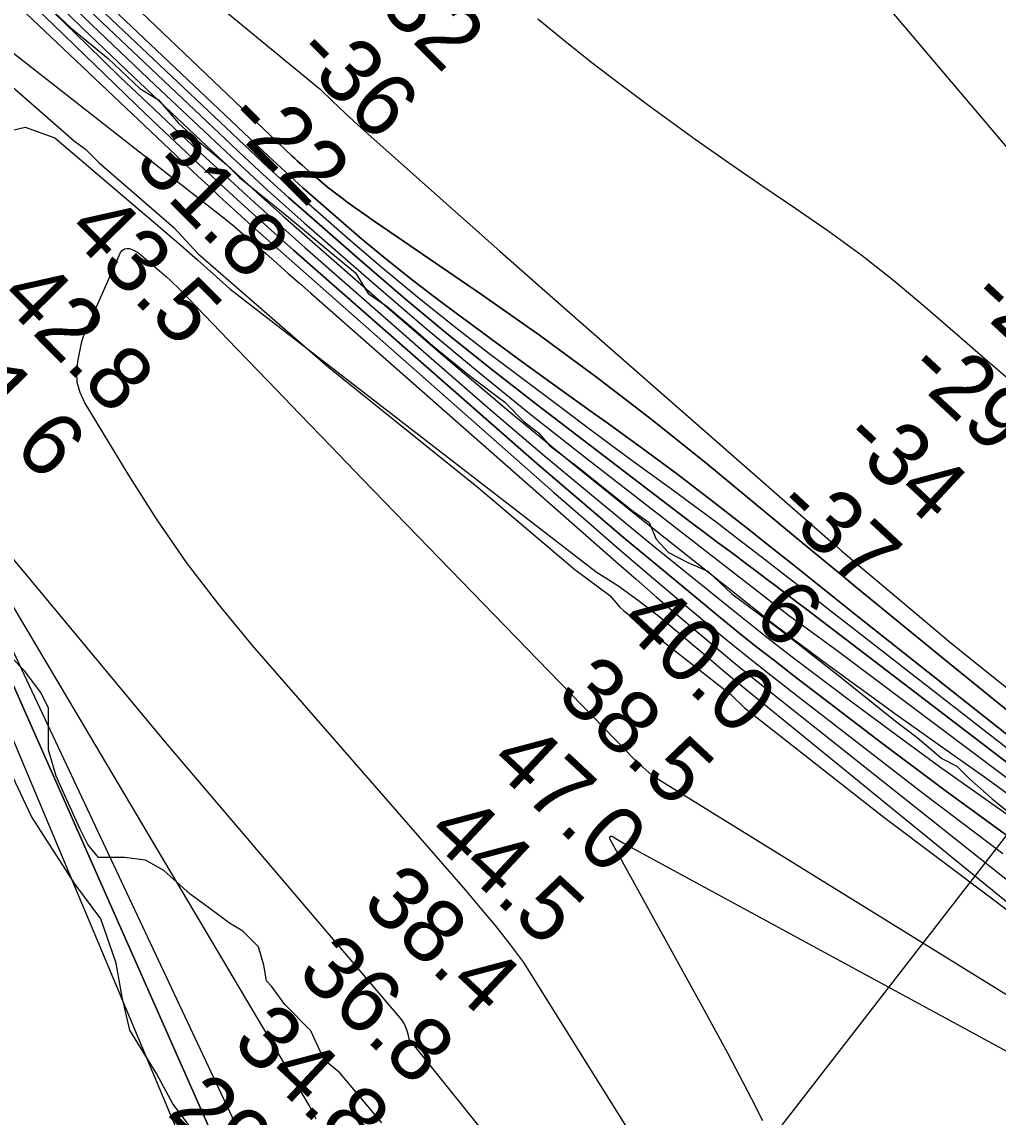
# Model space of a CAD drawing. Extents: x 3161615 to 3199515, y 867541 to 892976.
# Drawn here: x 3182704 to 3183730, y 881302 to 882454 of the extents above; entities that cross this region are included whole.
import ezdxf

# ---------------------------------------------------------------- set-up
doc = ezdxf.new("R2010")
doc.units = 0
for name, color, linetype in [('V-RIVR-EDGE', 7, 'Continuous'), ('V-RIVR-RANG', 7, 'Continuous'), ('V-SITE-VEGE', 7, 'Continuous'), ('V-TOPO-DPTH', 7, 'Continuous'), ('V-TOPO-MAJR', 7, 'Continuous'), ('V-TOPO-MINR', 7, 'Continuous'), ('V-TOPO-WATR', 7, 'Continuous')]:
    doc.layers.add(name, color=color, linetype=linetype)

msp = doc.modelspace()

# ---------------------------------------------------------------- linework, layer by layer
at = {"layer": 'V-RIVR-EDGE'}
for points in [[(3182726.1, 882475.2), (3182755.5, 882447.5), (3182794.6, 882415.5), (3182827.9, 882383.9), (3182847.4, 882371.9), (3182868.3, 882347.6), (3182888.8, 882328.9), (3182918.8, 882304), (3182932.6, 882290.2), (3182984, 882248.6), (3183026.3, 882213.2), (3183054.4, 882190.2), (3183067.7, 882168.2), (3183087.7, 882154.8), (3183120.5, 882127.1), (3183135.7, 882113.2), (3183174.8, 882081.7), (3183211.4, 882053.9), (3183231.9, 882033.4), (3183247.1, 882021.9), (3183258.5, 882008.5), (3183291.8, 881983.1), (3183298, 881977.9), (3183347, 881939.1), (3183363.2, 881927.6), (3183370.8, 881910), (3183383.7, 881896.1), (3183404.1, 881885.6), (3183425.1, 881876.5), (3183450.3, 881852.6), (3183500.3, 881815.2), (3183565.5, 881764), (3183622.1, 881719.1), (3183645, 881701.4), (3183671.2, 881679.4), (3183686.9, 881671.2), (3183700.2, 881657.8), (3183724, 881636.8), (3183748.3, 881617.2)], [(3182845.3, 881348.1), (3182817.3, 881393.5), (3182809.3, 881428.3), (3182802.7, 881464.1), (3182786.6, 881510.8), (3182759.5, 881547.6), (3182713.9, 881618.3), (3182677.4, 881695.2)], [(3182880, 881293.2), (3182862.4, 881316.1), (3182845.3, 881348.1)]]:
    msp.add_lwpolyline(points, dxfattribs=at)
at = {"layer": 'V-RIVR-RANG'}
msp.add_line((3181801.2, 879095.8), (3184051.7, 882002.4), dxfattribs=at)
at = {"layer": 'V-SITE-VEGE'}
for points in [[(3182582.5, 882483.1), (3182759, 882328.7), (3182770.5, 882320), (3182784.9, 882305.8), (3182863.6, 882237.7), (3182888.8, 882210.5), (3183025.9, 882091.1), (3183183.9, 881963.9), (3183285.3, 881878), (3183322.1, 881850.8), (3183332.3, 881838.5), (3183336.3, 881835), (3183449.1, 881746.6), (3183463.7, 881732.6), (3183610.1, 881617.8), (3183727.1, 881529.7), (3183827.7, 881452.8)], [(3183082.3, 881296.3), (3183038.1, 881348.8), (3183021.5, 881362.6), (3183007.7, 881393), (3182980.1, 881420.6), (3182966.3, 881439.9), (3182960.8, 881445.4), (3182958, 881462), (3182952.5, 881481.3), (3182935.9, 881497.9), (3182922.1, 881506.2), (3182900.1, 881522.8), (3182880.7, 881536.6), (3182853.1, 881561.4), (3182833.8, 881572.5), (3182811.7, 881575.2), (3182784.1, 881575.2), (3182773.1, 881589), (3182764.8, 881605.6), (3182751, 881636), (3182739.9, 881660.8), (3182731.7, 881688.5), (3182731.7, 881732.6), (3182723.4, 881749.2), (3182706.8, 881771.3), (3182693, 881785.1)]]:
    msp.add_lwpolyline(points, dxfattribs=at)
at = {"layer": 'V-TOPO-DPTH'}
for points in [[(3183742, 881596.5), (3183674.6, 881645.7), (3183607.8, 881695.8), (3183515.3, 881766.4), (3183495.3, 881781.9), (3183475.3, 881797.6), (3183455.5, 881813.4), (3183435.8, 881829.5), (3183382.5, 881873.5), (3183336.4, 881911.8), (3183290.6, 881950.5), (3183245.1, 881989.6), (3183199.9, 882029), (3182989.4, 882214), (3182965.5, 882235.3), (3182941.6, 882256.7), (3182917.9, 882278.4), (3182894.4, 882300.1), (3182871, 882322.1), (3182847.7, 882344.1), (3182824.5, 882366.2), (3182801.4, 882388.5), (3182368.3, 882807.3)], [(3182509.3, 882800.7), (3183017.5, 882383.2), (3183030.5, 882370.6), (3183043.7, 882358.1), (3183057.1, 882345.8), (3183070.5, 882333.6), (3183124.8, 882285.2), (3183165.5, 882249), (3183206.3, 882212.8), (3183247.2, 882176.7), (3183288.2, 882140.8), (3183553.9, 881907.9), (3183559.8, 881902.9), (3183565.6, 881897.8), (3183571.5, 881892.8), (3183577.3, 881887.8), (3183622.9, 881849.2), (3183651.7, 881825.1), (3183680.6, 881801.1), (3183709.7, 881777.4), (3183739, 881753.9), (3183778.6, 881722.3)], [(3182509.3, 882800.7), (3183017.5, 882383.2), (3183030.5, 882370.6), (3183043.7, 882358.1), (3183057.1, 882345.8), (3183070.5, 882333.6), (3183124.8, 882285.2), (3183165.5, 882249), (3183206.3, 882212.8), (3183247.2, 882176.7), (3183288.2, 882140.8), (3183553.9, 881907.9), (3183559.8, 881902.9), (3183565.6, 881897.8), (3183571.5, 881892.8), (3183577.3, 881887.8), (3183622.9, 881849.2), (3183651.7, 881825.1), (3183680.6, 881801.1), (3183709.7, 881777.4), (3183739, 881753.9)], [(3182579.5, 882702.2), (3182988, 882312.9), (3182990.6, 882310.4), (3182993.2, 882308), (3182995.9, 882305.5), (3182998.5, 882303.2), (3183009, 882293.9), (3183017, 882287), (3183025.1, 882280.3), (3183033.5, 882273.8), (3183041.9, 882267.4), (3183044.5, 882265.6), (3183054.3, 882258.5), (3183064.2, 882251.5), (3183074.1, 882244.5), (3183084.1, 882237.6), (3183187, 882167.3), (3183247.9, 882124.4), (3183308, 882080.5), (3183366.8, 882035), (3183424.9, 881988.4), (3183525.4, 881905.4), (3183539, 881894.2), (3183552.5, 881883), (3183566.1, 881871.9), (3183579.7, 881860.7), (3183667.8, 881788.4), (3183725.6, 881741.3), (3183783.7, 881694.6)], [(3183768.4, 881706.9), (3183725.6, 881741.3), (3183667.8, 881788.4), (3183579.7, 881860.7), (3183566.1, 881871.9), (3183552.5, 881883), (3183539, 881894.2), (3183525.4, 881905.4), (3183424.9, 881988.4), (3183366.8, 882035), (3183308, 882080.5), (3183247.9, 882124.4), (3183187, 882167.3), (3183084.1, 882237.6), (3183074.1, 882244.5), (3183064.2, 882251.5), (3183054.3, 882258.5), (3183044.5, 882265.6), (3183041.9, 882267.4), (3183033.5, 882273.8), (3183025.1, 882280.3), (3183017, 882287), (3183009, 882293.9), (3182998.5, 882303.2), (3182995.9, 882305.5), (3182993.2, 882308), (3182990.6, 882310.4), (3182988, 882312.9), (3182579.5, 882702.2)], [(3182293.8, 882669.9), (3182441, 882190.9), (3182448.4, 882170.4), (3182457, 882150.5), (3182467.3, 882131.5), (3182478.8, 882113), (3182579.7, 881966.6), (3182593.9, 881946.1), (3182608.2, 881925.6), (3182622.7, 881905.3), (3182637.3, 881885), (3182925.1, 881235.7)], [(3183452.3, 882661), (3183796.2, 882255)], [(3183452.3, 882661), (3183796.2, 882255)], [(3183797.7, 881658.7), (3183715.6, 881723.5), (3183582.9, 881828.8), (3183559.9, 881847), (3183536.9, 881865.3), (3183513.9, 881883.6), (3183490.9, 881901.9), (3183464.8, 881922.7), (3183428.5, 881951.1), (3183392, 881979.1), (3183354.9, 882006.5), (3183317.6, 882033.5), (3183303.9, 882043.2), (3183267.5, 882069.3), (3183231.2, 882095.6), (3183195.1, 882122), (3183159.1, 882148.7), (3183144, 882159.9), (3183115.9, 882181.4), (3183088.1, 882203.3), (3183060.9, 882225.9), (3183034.1, 882249), (3182999.3, 882279.6), (3182990.1, 882287.7), (3182981.1, 882295.9), (3182972.1, 882304.2), (3182963.2, 882312.6), (3182707.9, 882554.7)], [(3183797.7, 881658.7), (3183715.6, 881723.5), (3183582.9, 881828.8), (3183559.9, 881847), (3183536.9, 881865.3), (3183513.9, 881883.6), (3183490.9, 881901.9), (3183464.8, 881922.7), (3183428.5, 881951.1), (3183392, 881979.1), (3183354.9, 882006.5), (3183317.6, 882033.5), (3183303.9, 882043.2), (3183267.5, 882069.3), (3183231.2, 882095.6), (3183195.1, 882122), (3183159.1, 882148.7), (3183144, 882159.9), (3183115.9, 882181.4), (3183088.1, 882203.3), (3183060.9, 882225.9), (3183034.1, 882249), (3182999.3, 882279.6), (3182990.1, 882287.7), (3182981.1, 882295.9), (3182972.1, 882304.2), (3182963.2, 882312.6), (3182707.9, 882554.7)], [(3182720.6, 882493.2), (3182766.9, 882447.9), (3182813.6, 882403.1), (3182860.6, 882358.6), (3182910.6, 882311.7), (3182932.9, 882291), (3182955.4, 882270.4), (3182978.1, 882250.1), (3183000.9, 882229.9), (3183085.6, 882155.8), (3183151.2, 882099.2), (3183217.4, 882043.2), (3183284.4, 881988.2), (3183351.9, 881933.8), (3183479.9, 881832.1), (3183487.8, 881825.8), (3183495.9, 881819.6), (3183503.9, 881813.5), (3183512, 881807.4), (3183545.4, 881782.5), (3183570.3, 881764.2), (3183595.2, 881745.9), (3183620.3, 881727.8), (3183645.5, 881709.8), (3183675.6, 881688.6), (3183715.8, 881659.9), (3183755.8, 881631.1)], [(3182720.6, 882493.2), (3182766.9, 882447.9), (3182813.6, 882403.1), (3182860.6, 882358.6), (3182910.6, 882311.7), (3182932.9, 882291), (3182955.4, 882270.4), (3182978.1, 882250.1), (3183000.9, 882229.9), (3183085.6, 882155.8), (3183151.2, 882099.2), (3183217.4, 882043.2), (3183284.4, 881988.2), (3183351.9, 881933.8), (3183479.9, 881832.1), (3183487.8, 881825.8), (3183495.9, 881819.6), (3183503.9, 881813.5), (3183512, 881807.4), (3183545.4, 881782.5), (3183570.3, 881764.2), (3183595.2, 881745.9), (3183620.3, 881727.8), (3183645.5, 881709.8), (3183675.6, 881688.6), (3183715.8, 881659.9), (3183755.8, 881631.1)], [(3182756.3, 882483.9), (3182826.6, 882416.7), (3182937.4, 882312.2), (3182952.9, 882297.7), (3182968.5, 882283.4), (3182984.2, 882269.3), (3183000.1, 882255.2), (3183058.9, 882203.8), (3183104.7, 882164.6), (3183150.9, 882126), (3183197.9, 882088.4), (3183245.4, 882051.3), (3183394.6, 881937.4), (3183408, 881927.2), (3183421.4, 881917.1), (3183434.9, 881907), (3183448.4, 881896.9), (3183453.7, 881893), (3183464.6, 881884.9), (3183475.4, 881876.8), (3183486.1, 881868.7), (3183496.8, 881860.5), (3183507.5, 881852.4), (3183518.3, 881844.2), (3183529, 881836), (3183539.7, 881827.8), (3183856.4, 881585.9)], [(3183856.4, 881585.9), (3183539.7, 881827.8), (3183529, 881836), (3183518.3, 881844.2), (3183507.5, 881852.4), (3183496.8, 881860.5), (3183486.1, 881868.7), (3183475.4, 881876.8), (3183464.6, 881884.9), (3183453.7, 881893), (3183448.4, 881896.9), (3183434.9, 881907), (3183421.4, 881917.1), (3183408, 881927.2), (3183394.6, 881937.4), (3183245.4, 882051.3), (3183197.9, 882088.4), (3183150.9, 882126), (3183104.7, 882164.6), (3183058.9, 882203.8), (3183000.1, 882255.2), (3182984.2, 882269.3), (3182968.5, 882283.4), (3182952.9, 882297.7), (3182937.4, 882312.2), (3182826.6, 882416.7), (3182756.3, 882483.9)], [(3183738.6, 882080.5), (3183714.2, 882101.4), (3183689.9, 882122.4), (3183653.5, 882154), (3183620.7, 882181.5), (3183587.2, 882208.1), (3183552.7, 882233.2), (3183517.5, 882257.5), (3183481.9, 882281.4), (3183446.6, 882305.6), (3183411.6, 882330.3), (3183376.9, 882355.4), (3183361.4, 882366.8), (3183332.2, 882388.7), (3183303.2, 882410.9), (3183274.6, 882433.6), (3183246.3, 882456.7)], [(3183738.6, 882080.5), (3183714.2, 882101.4), (3183689.9, 882122.4), (3183653.5, 882154), (3183620.7, 882181.5), (3183587.2, 882208.1), (3183552.7, 882233.2), (3183517.5, 882257.5), (3183481.9, 882281.4), (3183446.6, 882305.6), (3183411.6, 882330.3), (3183376.9, 882355.4), (3183361.4, 882366.8), (3183332.2, 882388.7), (3183303.2, 882410.9), (3183274.6, 882433.6), (3183246.3, 882456.7)]]:
    msp.add_lwpolyline(points, dxfattribs=at)
at = {"layer": 'V-TOPO-MAJR'}
for points in [[(3182664.5, 882333.1), (3182707.1, 882343.1), (3182738.2, 882332.1), (3182853.9, 882233.7), (3182871.2, 882218.8), (3182888.4, 882203.8), (3182905.3, 882188.6), (3182922.2, 882173.3), (3183307.6, 881875.6), (3183330.4, 881861.3), (3183352.2, 881845.6), (3183373.4, 881829), (3183398.6, 881807.9), (3183406.7, 881801.1), (3183414.8, 881794.3), (3183422.8, 881787.5), (3183430.8, 881780.7), (3183438.9, 881773.8), (3183447, 881767.1), (3183455.1, 881760.3), (3183463.2, 881753.7), (3183998.2, 881317.8)], [(3183646.8, 880717.5), (3183111.1, 881384.2), (3183110.9, 881384.6), (3183110.3, 881387.7), (3183110.1, 881388.2), (3183108.4, 881394.1), (3183107.2, 881397.4), (3183105.7, 881400.6), (3183103.8, 881403.6), (3183101.6, 881406.5), (3182856.5, 881694.4), (3182643, 881951)]]:
    msp.add_lwpolyline(points, dxfattribs=at)
at = {"layer": 'V-TOPO-MINR'}
for points in [[(3182368.3, 882807.3), (3182801.4, 882388.5), (3182824.5, 882366.2), (3182847.7, 882344.1), (3182871, 882322.1), (3182894.4, 882300.1), (3182917.9, 882278.4), (3182941.6, 882256.7), (3182965.5, 882235.3), (3182989.4, 882214), (3183199.9, 882029), (3183245.1, 881989.6), (3183290.6, 881950.5), (3183336.4, 881911.8), (3183382.5, 881873.5), (3183435.8, 881829.5), (3183455.5, 881813.4), (3183475.3, 881797.6), (3183495.3, 881781.9), (3183515.3, 881766.4), (3183607.8, 881695.8), (3183674.6, 881645.7), (3183742, 881596.5)], [(3182509.3, 882800.7), (3183017.5, 882383.2), (3183030.5, 882370.6), (3183043.7, 882358.1), (3183057.1, 882345.8), (3183070.5, 882333.6), (3183124.8, 882285.2), (3183165.5, 882249), (3183206.3, 882212.8), (3183247.2, 882176.7), (3183288.2, 882140.8), (3183553.9, 881907.9), (3183559.8, 881902.9), (3183565.6, 881897.8), (3183571.5, 881892.8), (3183577.3, 881887.8), (3183622.9, 881849.2), (3183651.7, 881825.1), (3183680.6, 881801.1), (3183709.7, 881777.4), (3183739, 881753.9)], [(3183783.7, 881694.6), (3183725.6, 881741.3), (3183667.8, 881788.4), (3183579.7, 881860.7), (3183566.1, 881871.9), (3183552.5, 881883), (3183539, 881894.2), (3183525.4, 881905.4), (3183424.9, 881988.4), (3183366.8, 882035), (3183308, 882080.5), (3183247.9, 882124.4), (3183187, 882167.3), (3183084.1, 882237.6), (3183074.1, 882244.5), (3183064.2, 882251.5), (3183054.3, 882258.5), (3183044.5, 882265.6), (3183041.9, 882267.4), (3183033.5, 882273.8), (3183025.1, 882280.3), (3183017, 882287), (3183009, 882293.9), (3182998.5, 882303.2), (3182995.9, 882305.5), (3182993.2, 882308), (3182990.6, 882310.4), (3182988, 882312.9), (3182579.5, 882702.2)], [(3183469, 879013.6), (3183197.7, 880018.7), (3183198.1, 880021.4), (3183197.8, 880022.8), (3183196, 880027.2), (3183194.9, 880029.5), (3183193.6, 880031.8), (3183192.2, 880034.1), (3183181.6, 880049.9), (3183030.2, 880674), (3182912.2, 881192.2), (3182899.3, 881211.2), (3182615.6, 881886.6), (3182596.4, 881913.9), (3182577.5, 881941.3), (3182558.6, 881968.9), (3182431.4, 882156.4), (3182416.9, 882180.1), (3182403.8, 882204.5), (3182393, 882229.9), (3182383.6, 882256.1), (3182375, 882284.4), (3182269.1, 882673.7)], [(3182925.1, 881235.7), (3182637.3, 881885), (3182622.7, 881905.3), (3182608.2, 881925.6), (3182593.9, 881946.1), (3182579.7, 881966.6), (3182478.8, 882113), (3182467.3, 882131.5), (3182457, 882150.5), (3182448.4, 882170.4), (3182441, 882190.9), (3182293.8, 882669.9)], [(3183452.3, 882661), (3183796.2, 882255)], [(3182707.9, 882554.7), (3182963.2, 882312.6), (3182972.1, 882304.2), (3182981.1, 882295.9), (3182990.1, 882287.7), (3182999.3, 882279.6), (3183034.1, 882249), (3183060.9, 882225.9), (3183088.1, 882203.3), (3183115.9, 882181.4), (3183144, 882159.9), (3183159.1, 882148.7), (3183195.1, 882122), (3183231.2, 882095.6), (3183267.5, 882069.3), (3183303.9, 882043.2), (3183317.6, 882033.5), (3183354.9, 882006.5), (3183392, 881979.1), (3183428.5, 881951.1), (3183464.8, 881922.7), (3183490.9, 881901.9), (3183513.9, 881883.6), (3183536.9, 881865.3), (3183559.9, 881847), (3183582.9, 881828.8), (3183715.6, 881723.5), (3183797.7, 881658.7)], [(3182726.6, 882499.9), (3182784.9, 882443.6), (3182843.6, 882387.7), (3182924.1, 882312), (3182943, 882294.4), (3182962, 882277), (3182981.2, 882259.8), (3183000.5, 882242.7), (3183071.5, 882180.8), (3183126.8, 882133.4), (3183182.7, 882086.6), (3183239.3, 882040.8), (3183296.5, 881995.7), (3183504.9, 881834), (3183506.2, 881833), (3183510, 881830.1), (3183514.8, 881826.6), (3183518.5, 881823.9), (3183522.2, 881821.2), (3183526, 881818.5), (3183529.7, 881815.8), (3183536.6, 881810.7), (3183543.8, 881805.5), (3183550.9, 881800.3), (3183558.1, 881795), (3183565.2, 881789.7), (3183924.2, 881520.7)], [(3182949.6, 881249.7), (3182639.4, 881908.7), (3182629.3, 881922.6), (3182619.2, 881936.5), (3182609.2, 881950.6), (3182599.3, 881964.6), (3182525.9, 882069.6), (3182517.6, 882082.8), (3182510.1, 882096.5), (3182503.8, 882110.8), (3182456.4, 882208.2), (3182369.2, 882483.9)], [(3182756.3, 882483.9), (3182826.6, 882416.7), (3182937.4, 882312.2), (3182952.9, 882297.7), (3182968.5, 882283.4), (3182984.2, 882269.3), (3183000.1, 882255.2), (3183058.9, 882203.8), (3183104.7, 882164.6), (3183150.9, 882126), (3183197.9, 882088.4), (3183245.4, 882051.3), (3183394.6, 881937.4), (3183408, 881927.2), (3183421.4, 881917.1), (3183434.9, 881907), (3183448.4, 881896.9), (3183453.7, 881893), (3183464.6, 881884.9), (3183475.4, 881876.8), (3183486.1, 881868.7), (3183496.8, 881860.5), (3183507.5, 881852.4), (3183518.3, 881844.2), (3183529, 881836), (3183539.7, 881827.8), (3183856.4, 881585.9)], [(3182772.3, 882480.9), (3182950.4, 882312.4), (3182962.6, 882301), (3182974.8, 882289.7), (3182987.2, 882278.6), (3182999.7, 882267.5), (3183046.5, 882226.4), (3183082.8, 882195.3), (3183119.6, 882164.7), (3183157, 882134.9), (3183194.8, 882105.7), (3183267.5, 882050.9), (3183295.1, 882030.2), (3183322.7, 882009.7), (3183350.5, 881989.3), (3183378.3, 881969), (3183385.9, 881963.5), (3183409.9, 881945.9), (3183433.7, 881928.1), (3183457.4, 881910), (3183481, 881891.8), (3183504.5, 881873.5), (3183528, 881855.2), (3183551.5, 881836.9), (3183575, 881818.6), (3183786.8, 881653.6)], [(3183013.3, 881300.1), (3183006.2, 881313.9), (3182635.3, 881938.6), (3182629.3, 881946.6), (3182623.5, 881954.7), (3182617.7, 881962.9), (3182572.8, 882026.2), (3182567.7, 882034.2), (3182563.1, 882042.5), (3182559.3, 882051.1), (3182556.1, 882060.1), (3182523.9, 882140.4), (3182476.6, 882285.8), (3182461.7, 882361), (3182461.8, 882408.6), (3182474.4, 882468.7)], [(3182708.2, 882462.9), (3182865.5, 882313.7), (3182876.9, 882302.9), (3182888.3, 882292.2), (3182899.8, 882281.4), (3182911.2, 882270.7), (3182922.8, 882260.1), (3182934.3, 882249.5), (3182946, 882239), (3182957.7, 882228.6), (3183262.8, 881959.5), (3183296.2, 881930.2), (3183329.7, 881901.2), (3183363.4, 881872.4), (3183397.3, 881843.8), (3183415.6, 881828.5), (3183440.6, 881807.8), (3183465.8, 881787.3), (3183491.1, 881767.1), (3183516.7, 881747.1), (3183651.7, 881642.7), (3183735.1, 881579.5)], [(3182737.8, 882463.5), (3182772.4, 882429.7), (3182807.2, 882396), (3182842.3, 882362.6), (3182877.5, 882329.4), (3182896.7, 882311.5), (3182922.6, 882287.5), (3182948.6, 882263.7), (3182974.8, 882240.2), (3183001.2, 882216.8), (3183139.6, 882095.4), (3183196.2, 882046.4), (3183253.2, 881997.8), (3183310.8, 881949.8), (3183368.7, 881902.3), (3183457.1, 881830.7), (3183471.2, 881819.4), (3183485.3, 881808.2), (3183499.5, 881797.2), (3183513.8, 881786.3), (3183576.4, 881739), (3183622.3, 881704.8), (3183668.5, 881671), (3183715.1, 881637.8), (3183762, 881605)], [(3183738.6, 882080.5), (3183714.2, 882101.4), (3183689.9, 882122.4), (3183653.5, 882154), (3183620.7, 882181.5), (3183587.2, 882208.1), (3183552.7, 882233.2), (3183517.5, 882257.5), (3183481.9, 882281.4), (3183446.6, 882305.6), (3183411.6, 882330.3), (3183376.9, 882355.4), (3183361.4, 882366.8), (3183332.2, 882388.7), (3183303.2, 882410.9), (3183274.6, 882433.6), (3183246.3, 882456.7)], [(3182650.7, 882455.4), (3182919.4, 882245), (3182922.3, 882242.7), (3182925.2, 882240.4), (3182928, 882238.1), (3182930.9, 882235.7), (3182933.7, 882233.3), (3182936.5, 882230.9), (3182939.3, 882228.5), (3182942.1, 882226.1), (3182960.2, 882210.3), (3182972, 882199.9), (3182983.8, 882189.5), (3182995.7, 882179.2), (3183007.5, 882168.8), (3183328.6, 881886.3), (3183349.7, 881867.8), (3183370.8, 881849.5), (3183392, 881831.2), (3183413.3, 881813), (3183434.8, 881795), (3183456.3, 881777.1), (3183478, 881759.5), (3183499.9, 881742), (3183808.5, 881497.2)], [(3183689, 880733.3), (3183231.5, 881464.9), (3183216.7, 881484.3), (3183201.6, 881503.6), (3183186, 881522.4), (3183170.2, 881541.1), (3182946.3, 881798.3), (3182910.8, 881841.3), (3182876.9, 881885.5), (3182845.3, 881931.4), (3182815.3, 881978.4), (3182769.7, 882054.2), (3182765, 882064.4), (3182762, 882074.8), (3182761.4, 882085.7), (3182762.5, 882096.8), (3182766.9, 882117.7), (3182768.1, 882122.2), (3182768.8, 882124), (3182769.1, 882124.8), (3182807.5, 882211.3), (3182809.3, 882213.6), (3182811.5, 882215.2), (3182814.1, 882215.7), (3182817, 882215.6), (3182820.2, 882214.3), (3182823.3, 882212.9), (3182826.2, 882211.1), (3182828.9, 882209), (3182855.8, 882185.7), (3182859.6, 882182.4), (3182863.3, 882179)], [(3182863.3, 882179), (3182866.9, 882175.5), (3182870.5, 882171.9), (3182929.5, 882110.4), (3182962.6, 882076), (3182995.7, 882041.7), (3183028.8, 882007.4), (3183061.9, 881973.2), (3183338.8, 881687.6), (3183347.6, 881678.7), (3183356.7, 881670.1), (3183366.1, 881661.8), (3184094.9, 881210.9)], [(3183482.7, 881298.3), (3183470.8, 881321.9), (3183458.6, 881345.3), (3183446.3, 881368.6), (3183433.8, 881391.8), (3183421.2, 881415), (3183321.9, 881595), (3183321.9, 881596.3), (3183322.2, 881597.2), (3183323.1, 881597.5), (3183324.4, 881597.5), (3183327.2, 881595.8), (3183330, 881594.1), (3183332.8, 881592.4), (3183335.5, 881590.5), (3184067.1, 881193.5)]]:
    msp.add_lwpolyline(points, dxfattribs=at)
at = {"layer": 'V-TOPO-WATR'}
msp.add_lwpolyline([(3182720.6, 882493.2), (3182766.9, 882447.9), (3182813.6, 882403.1), (3182860.6, 882358.6), (3182910.6, 882311.7), (3182932.9, 882291), (3182955.4, 882270.4), (3182978.1, 882250.1), (3183000.9, 882229.9), (3183085.6, 882155.8), (3183151.2, 882099.2), (3183217.4, 882043.2), (3183284.4, 881988.2), (3183351.9, 881933.8), (3183479.9, 881832.1), (3183487.8, 881825.8), (3183495.9, 881819.6), (3183503.9, 881813.5), (3183512, 881807.4), (3183545.4, 881782.5), (3183570.3, 881764.2), (3183595.2, 881745.9), (3183620.3, 881727.8), (3183645.5, 881709.8), (3183675.6, 881688.6), (3183715.8, 881659.9), (3183755.8, 881631.1)], dxfattribs=at)

# ---------------------------------------------------------------- texts
at = {"layer": 'V-RIVR-RANG'}
for s, rotation, p in [('-32', 314.8431, (3183056.7, 882490.3)), ('-36', 314.8431, (3182987.6, 882418)), ('-22', 314.8431, (3182915.2, 882349)), ('31.8', 314.6583, (3182820, 882303.4)), ('43.5', 314.6583, (3182749.1, 882232.9)), ('42.8', 314.6583, (3182678.1, 882162.5)), ('-23', 317.0767, (3183697.3, 882160.3)), ('41.6', 314.6583, (3182605.8, 882093.3)), ('-29', 317.0767, (3183631.6, 882084.8)), ('-34', 317.0767, (3183563.1, 882011.9)), ('-37', 317.0767, (3183492.9, 881940.7)), ('6', 317.0767, (3183470, 881825.4)), ('40.0', 316.9183, (3183329.8, 881819.7)), ('38.5', 316.9183, (3183263.8, 881744.5)), ('47.0', 316.9183, (3183193.5, 881673.3)), ('44.5', 316.9183, (3183127.5, 881598.1)), ('38.4', 316.9183, (3183059.4, 881524.9)), ('36.8', 316.9183, (3182991.3, 881451.7)), ('34.8', 316.9183, (3182923.1, 881378.5)), ('29.4', 316.9183, (3182855, 881305.3))]:
    msp.add_text(s, height=67, rotation=rotation, dxfattribs=at).set_placement(p)

doc.saveas('drawing.dxf')
